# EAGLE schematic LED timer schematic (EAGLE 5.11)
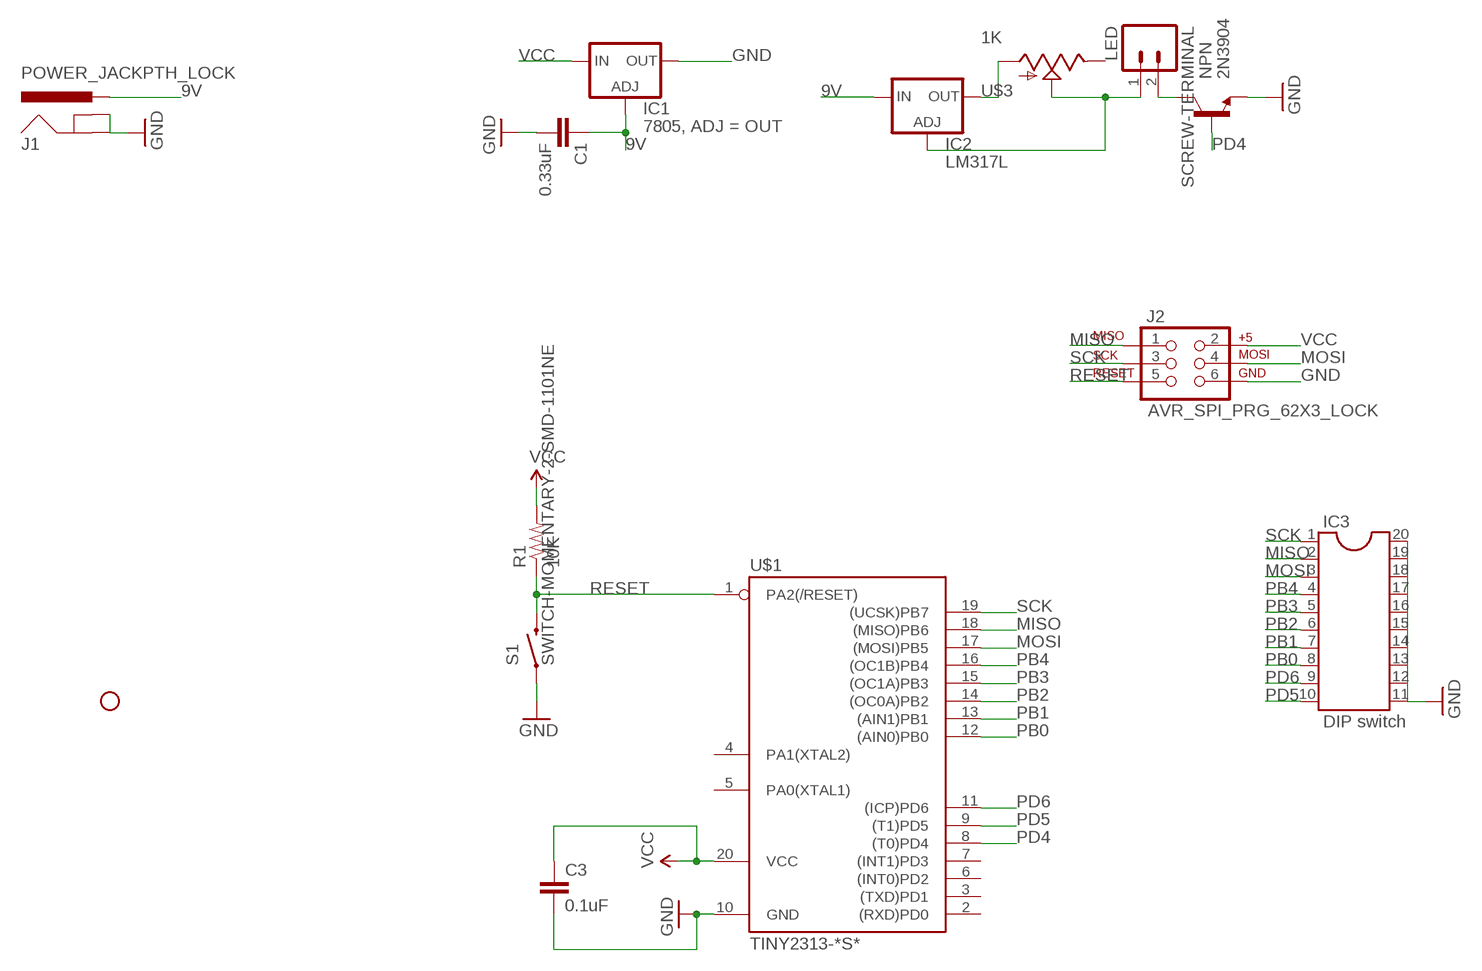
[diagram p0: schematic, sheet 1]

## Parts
C1  0.33uF  CAP1206  [1206]
C3  0.1uF  CAP1206  [1206]
IC1  7805, ADJ = OUT  LM317MBSTT3  [SOT223]
IC2  LM317L  LM317MSTT3  [SOT223]
IC3  DIP switch  DIL20  [DIL20]
J1  POWER_JACKPTH_LOCK  [POWER_JACK_PTH_LOCK]
J2  AVR_SPI_PRG_62X3_LOCK  [2X3_LOCK]
JP4  STAND-OFF  [STAND-OFF]
NPN  2N3904  TRANSISTOR_NPNSOT23  [SOT23]
R1  10K  RESISTOR1206  [1206]
S1  SWITCH-MOMENTARY-2-SMD-1101NE  [TACTILE-SWITCH-1101NE]
SCREW-TERMINAL  LED  M02LOCK  [1X02_LOCK]
U$1  TINY2313-*S*  [SO20L$]
U$3  1K  POT100K_3362U  [3362U]

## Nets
9V: C1.1 IC1.1(ADJ) IC2.3(IN) J1.PWR
GND: C1.2 C3.2 IC1.4(OUT) IC3.11 IC3.12 IC3.13 IC3.14 IC3.15 IC3.16 IC3.17 IC3.18 IC3.19 IC3.20 J1.GND J1.GNDBREAK J2.6 NPN.2(E) S1.P$1 U$1.10(GND)
MISO: IC3.2 J2.1 U$1.18((MISO)PB6)
MOSI: IC3.3 J2.4 U$1.17((MOSI)PB5)
N$1: IC2.4(OUT) U$3.P$3(A)
N$2: IC2.1(ADJ) SCREW-TERMINAL.1 U$3.P$2(S)
N$4: NPN.3(C) SCREW-TERMINAL.2
PB0: IC3.8 U$1.12((AIN0)PB0)
PB1: IC3.7 U$1.13((AIN1)PB1)
PB2: IC3.6 U$1.14((OC0A)PB2)
PB3: IC3.5 U$1.15((OC1A)PB3)
PB4: IC3.4 U$1.16((OC1B)PB4)
PD4: NPN.1(B) U$1.8((T0)PD4)
PD5: IC3.10 U$1.9((T1)PD5)
PD6: IC3.9 U$1.11((ICP)PD6)
RESET: J2.5 R1.1 S1.P$2 U$1.1(PA2(/RESET))
SCK: IC3.1 J2.3 U$1.19((UCSK)PB7)
VCC: C3.1 IC1.3(IN) J2.2 R1.2 U$1.20(VCC)
Unconnected: U$1.2((RXD)PD0) U$1.3((TXD)PD1) U$1.4(PA1(XTAL2)) U$1.5(PA0(XTAL1)) U$1.6((INT0)PD2) U$1.7((INT1)PD3) U$3.P$1(E)

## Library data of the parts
C1 C3 = SparkFun:CAP: Capacitor
IC1 IC2 = v-reg:LM317?*: 500 mA Adjustable Output Positive Voltage Regulator Source: http://www.onsemi.co.jp .. LM317M-D.PDF
IC3 = ic-package:DIL20: Dual In Line / Socket
J1 = SparkFun:POWER_JACK: Power Jack This is the standard 5.5mm barrel jack for power. The PTH is the most common, proven, reliable, footprint. All others are experimental. The Slot footprint only works if the mill layer is transmitted to the PCB fab house so be warned. Spark Fun Electronics SKU : PRT-00119. Mating wall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
J2 = SparkFun:AVR_SPI_PRG_6: AVR ISP 6 Pin This is the reduced ISP connector for AVR programming. Common on Arduino. This footprint will take up less PCB space and can be used with a 10-pin to 6-pin adapter such as SKU: BOB-08508
JP4 = SparkFun:STAND-OFF: Stand Off
NPN = SparkFun:TRANSISTOR_NPN: Transistor NPN BJT configuration in SOT23 package. MMBT2222 is the common NPN we use. Double check BCE configuration again layout.
R1 = SparkFun:RESISTOR: Resistor
S1 = SparkFun:SWITCH-MOMENTARY-2
SCREW-TERMINAL = SparkFun:M02: Header 2
U$1 = avr-6:TINY2313*: Atmel Tiny2313 2K Flash, 128 bytes EEPROM, 128 bytes RAM
U$3 = SparkFun:POT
